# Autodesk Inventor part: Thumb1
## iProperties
Company: cbliss@cbliss.com
Author: Charles Bliss
Shininess: 0.0
PropertySet Name: _Private Model Information
Created: 2000-01
Part Number: Thumb1
Project: Inventor Sample
Document SubType Name: Modeling
Designer: Charles Bliss
Control State: 0
Master: False
Checked Out: False
Density: 0.0
Volume: 0.0
Area: 0.0
PropertySet Name: Model Information
